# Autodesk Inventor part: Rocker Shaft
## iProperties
Created: 2005-03
Part Number: Rocker Shaft
Document SubType Name: Modeling
Designer: brent
Density: 1 g/cm^3
Author: Autodesk Inc.
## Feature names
1. Extrusion1
